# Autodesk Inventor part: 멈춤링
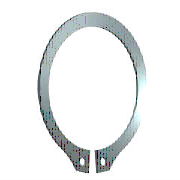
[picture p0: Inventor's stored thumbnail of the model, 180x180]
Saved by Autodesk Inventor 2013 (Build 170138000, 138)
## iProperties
Created: 2014-12
Part Number: 멈춤링
Material: 강, 연강
Description: 리테이닝 링(C형)
Document SubType Name: Modeling
Standard: KS B 1336
Designer: KYOUNG IL JANG
Standards Organization: KS
Language: ko-KR
Size Designation: 17 x 1
Categories: <MemberInstance><Categories><Category DisplayName="샤프트 부품" InternalName="7f7aeb1f-a693-4053-b835-cee3144e0d98" Mnemonic="SHFT"><Category DisplayName="써클립" Inter
Density: 7.86 g/cm^3
Mass: 0.979804 g
Surface Area: 3.83537 cm^2
Volume: 0.124657 cm^3
Company: 한국ATC센터
Author: KYOUNG IL JANG
IsCustomPart: 0
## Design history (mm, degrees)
sketch "스케치1"
  geometry: L1 (-6, 0)-(6, 0) reference; L2 (0, 20.189)-(0, -80.536) reference; L3 (-48.09, 0)-(48.09, 0) reference; L4 (-0.425, -16.589)-(-0.425, -20.289); L5 (-0.425, -6.54)-(-0.425, -13.29); L6 (-2.795, 2.2)-(3.672, 2.2); L7 (0.425, -6.54)-(0.425, -13.29); L8 (0.425, -16.589)-(0.425, -20.289); C1 r 0.85 at (-1.7, -18.452); C2 r 0.85 at (1.7, -18.452); A1 r 8.1 centre (0, -8.5) between (0.425, -16.589) and (-0.425, -16.589); A2 r 10.15 centre (0, -7.95) between (4.363, -17.114) and (-4.363, -17.114); A3 r 11.797 centre (0, -8.5) between (-1.986, -20.128) and (-0.425, -20.289); A4 r 1.7 centre (-1.7, -18.452) between (-3.397, -18.551) and (-1.986, -20.128); A5 r 1.7 centre (-5.094, -18.649) between (-3.397, -18.551) and (-4.363, -17.114); A6 r 1.7 centre (5.094, -18.649) between (4.363, -17.114) and (3.397, -18.551); A7 r 1.7 centre (1.7, -18.452) between (1.986, -20.128) and (3.397, -18.551); A8 r 11.797 centre (0, -8.5) between (0.425, -20.289) and (1.986, -20.128)
  constraints: 16 point on circle, 12 end point, 10 centre point, 9 symmetric about line, 5 point on line, 4 tangent, 3 coincident, 2 horizontal, 1 perpendicular, 1 vertical, 5 other
  dimensions: "d0" = 16.2 diameter of A1 (= ND); "d1" = 3.7 distance of L4.end L4.start (= SRB2); "d6" = 0.425 distance between parallel lines of L2 L5 (= 0.25 x SD5); "d7" = 2.2 distance between parallel lines of L6 L3 (= SRB1); "d8" = 0.55 distance of A1.centre A2.centre (= 0.25 x SRB1); "d9" = 1.7 radius of A4 (= SD5); "d10" = 1.7 radius of A5 (= SD5); "d11" = 1.275 distance from line of L4 A4.centre (= 0.75 x SD5); "d12" = 1.7 diameter of C1 (= SD5); "d13" = 1.7 diameter of C2 (= SD5); "d14" = 8.5 distance from line of A1.centre L1 (= 0.5 x WD)
extrude "본체" new body sketch "스케치1" distance "d2" = 1 (= SD); taper "d3" = 0 deg
workaxis "Work Axis1"
workplane "Work Plane1"
body "Solid1"
other parameters: "WD" = 17 (= WDMIN) [user parameter; used in 1 equation term], "SD" = 1 [user parameter; used in 1 equation term], "SRB1" = 2.2 [user parameter; used in 2 equation terms], "ND" = 16.2 [user parameter; used in 1 equation term], "SRB2" = 3.7 [user parameter; used in 1 equation term], "SD5" = 1.7 [user parameter; used in 6 equation terms], "d15" = 0, "d16" = 0, "d17" = 0, "d41" = 0, "d42" = 0, "WDMIN" = 17 [user parameter; used in 1 equation term], "SD3" = 15.7 [user parameter], "WDMAX" = 18 [user parameter]
